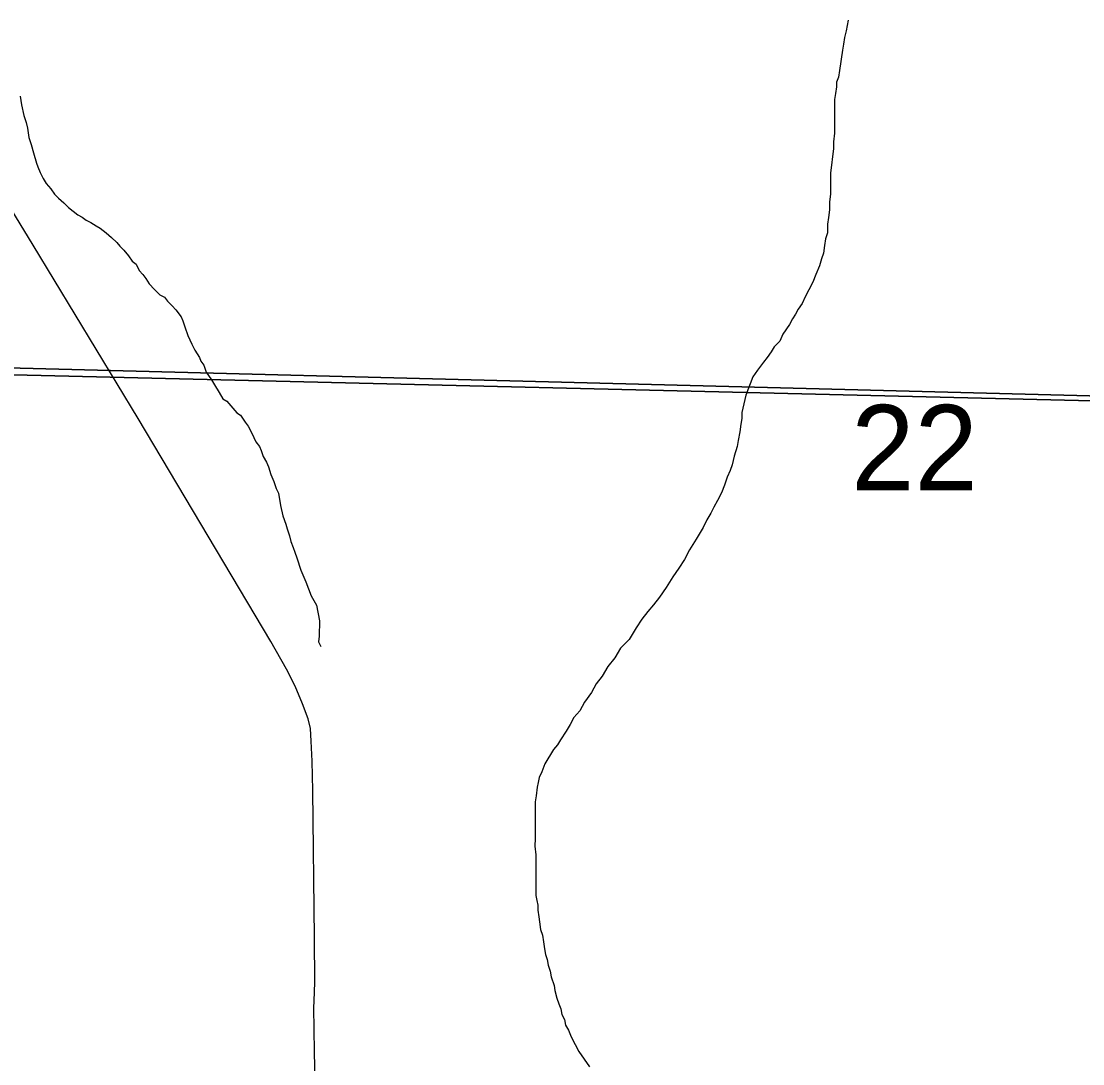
# Model space of a CAD drawing. Extents: x 0 to 68, y 0 to 52.9.
# Drawn here: x 47.168 to 47.718, y 37.512 to 38.053 of the extents above; entities that cross this region are included whole.
import ezdxf

# ---------------------------------------------------------------- set-up
doc = ezdxf.new("R2010")
doc.units = 0
for name, color, linetype in [('Default', 7, 'Continuous'), ('GM_X_Minor_River', 7, 'Continuous'), ('GM_X_Township', 7, 'Continuous'), ('GM_X_Township_Road', 7, 'Continuous')]:
    doc.layers.add(name, color=color, linetype=linetype)

msp = doc.modelspace()

# ---------------------------------------------------------------- linework, layer by layer
at = {"layer": 'Default'}
for points in [[(48.45764, 39.14733), (48.42638, 37.83913), (47.10596, 37.87106), (47.12776, 39.18296)], [(47.08147, 37.87185), (47.10596, 37.87106), (48.42638, 37.83913), (48.38433, 36.55233), (47.04294, 36.58651)]]:
    msp.add_lwpolyline(points, close=True, dxfattribs=at)
at = {"layer": 'GM_X_Minor_River'}
for points in [[(47.59672, 38.05354), (47.5957, 38.04803), (47.59469, 38.04452), (47.59418, 38.04101), (47.59367, 38.038), (47.59214, 38.02747), (47.59163, 38.02396), (47.59062, 38.02146), (47.59062, 38.01895), (47.59011, 38.01544), (47.5896, 38.01243), (47.58959, 38.00691), (47.58958, 38.0029), (47.58957, 37.99839), (47.58956, 37.99487), (47.58905, 37.99036), (47.58904, 37.98685), (47.58853, 37.98284), (47.58802, 37.97832), (47.58751, 37.97431), (47.58749, 37.96779), (47.58748, 37.96328), (47.58697, 37.95926), (47.58696, 37.95525), (47.58645, 37.95124), (47.58594, 37.94773), (47.58593, 37.94321), (47.58492, 37.94021), (47.58441, 37.9367), (47.5839, 37.93269), (47.58288, 37.92968), (47.58187, 37.92617), (47.57986, 37.92166), (47.57834, 37.91765), (47.57633, 37.91365), (47.57431, 37.91014), (47.5728, 37.90664), (47.57079, 37.90363), (47.56927, 37.90113), (47.56776, 37.89863), (47.56625, 37.89562), (47.56273, 37.89062), (47.56121, 37.88711), (47.5582, 37.88411), (47.55669, 37.88161), (47.55467, 37.8786), (47.55266, 37.8761), (47.54964, 37.8721), (47.54712, 37.86859), (47.54359, 37.85907), (47.54258, 37.85456), (47.54156, 37.85005), (47.54155, 37.84704), (47.54105, 37.84403), (47.54053, 37.84002), (47.53952, 37.83551), (47.53901, 37.8325), (47.5375, 37.82749), (47.53648, 37.82298), (47.53547, 37.81997), (47.53396, 37.81646), (47.53245, 37.81245), (47.53093, 37.80845), (47.52892, 37.80444), (47.5269, 37.80093), (47.52539, 37.79793), (47.52337, 37.79443), (47.52136, 37.79042), (47.51783, 37.78441), (47.51431, 37.7789), (47.51179, 37.77389), (47.50876, 37.76939), (47.50575, 37.76488), (47.50222, 37.75938), (47.4987, 37.75437), (47.49568, 37.75037)], [(47.16709, 38.01409), (47.16784, 38.00966), (47.16898, 38.00402), (47.17014, 38.00039), (47.17091, 37.99757), (47.17166, 37.99274), (47.17282, 37.98911)], [(47.17282, 37.98911), (47.17397, 37.98467), (47.17552, 37.97943), (47.1763, 37.97741), (47.17747, 37.97458), (47.17904, 37.97134), (47.18062, 37.96891), (47.183, 37.96607), (47.18498, 37.96323), (47.18697, 37.9612), (47.18976, 37.95875), (47.19214, 37.95631), (47.19693, 37.95263), (47.19933, 37.95139), (47.20133, 37.94976), (47.20373, 37.94852), (47.20653, 37.94688), (47.20853, 37.94564), (47.21172, 37.94319), (47.21451, 37.94074), (47.2173, 37.9383), (47.21888, 37.93627), (47.22087, 37.93423), (47.22325, 37.93139), (47.22523, 37.92855), (47.22722, 37.92692), (47.22879, 37.92368), (47.23078, 37.92164), (47.23237, 37.91961), (47.23394, 37.91678), (47.23673, 37.91393), (47.23951, 37.91108), (47.24191, 37.90985), (47.2435, 37.90782), (47.24589, 37.90537), (47.24787, 37.90334), (47.25065, 37.89969), (47.25143, 37.89767), (47.2526, 37.89444), (47.25415, 37.89), (47.25611, 37.88555), (47.25768, 37.88232), (47.26005, 37.87867), (47.26083, 37.87665), (47.26242, 37.87462), (47.26358, 37.87099), (47.26635, 37.86694), (47.26793, 37.8645), (47.27029, 37.86045), (47.27227, 37.85721), (47.27427, 37.85598), (47.27744, 37.85232), (47.27943, 37.84989), (47.28143, 37.84866), (47.2838, 37.84501), (47.28538, 37.84298), (47.28735, 37.83934), (47.28931, 37.83489), (47.29129, 37.83246), (47.29207, 37.83043), (47.29324, 37.82721), (47.29482, 37.82437), (47.29599, 37.82195), (47.29715, 37.81791), (47.29872, 37.81428), (47.29988, 37.81065), (47.30106, 37.80822), (47.30218, 37.80177), (47.30333, 37.79654), (47.30488, 37.7921), (47.30566, 37.78967), (47.30682, 37.78604), (47.30759, 37.78322), (47.30876, 37.77999), (47.30953, 37.77757), (47.31071, 37.77474), (47.31264, 37.76829), (47.31538, 37.76222), (47.31811, 37.75496), (47.32087, 37.7501), (47.32238, 37.74204), (47.32228, 37.73401), (47.32184, 37.7312), (47.32184, 37.7312), (47.32302, 37.72877)], [(47.49568, 37.75037), (47.49266, 37.74687), (47.48964, 37.74286), (47.48662, 37.73836), (47.48309, 37.73235), (47.47857, 37.72785), (47.47555, 37.72284), (47.47202, 37.71834), (47.469, 37.71333), (47.46598, 37.70933), (47.46346, 37.70482), (47.45994, 37.69981), (47.45742, 37.69531), (47.4544, 37.69181), (47.45239, 37.6883), (47.45037, 37.6848), (47.44735, 37.68029), (47.44584, 37.67779), (47.44383, 37.67529), (47.4393, 37.66778), (47.43778, 37.66377), (47.43627, 37.66076), (47.43576, 37.65826), (47.43526, 37.65575), (47.43474, 37.65123), (47.43423, 37.64823), (47.43423, 37.64572), (47.43422, 37.64271), (47.43421, 37.6397), (47.43421, 37.63669), (47.4342, 37.63268), (47.43419, 37.62916), (47.43418, 37.62515), (47.43467, 37.62064), (47.43466, 37.61712), (47.43465, 37.61261), (47.43464, 37.60759), (47.43463, 37.60308), (47.43462, 37.59957), (47.43512, 37.59706), (47.43561, 37.59454), (47.43561, 37.59204), (47.4361, 37.58853), (47.4366, 37.58601), (47.43709, 37.582), (47.43809, 37.57899), (47.43858, 37.57547), (47.43908, 37.57196), (47.43957, 37.56895), (47.44057, 37.56644), (47.44106, 37.56343), (47.44206, 37.56041), (47.44256, 37.5574), (47.44405, 37.55288), (47.44454, 37.55037), (47.44554, 37.54636), (47.44654, 37.54334), (47.44753, 37.54083), (47.44803, 37.53782), (47.44953, 37.53531), (47.45002, 37.53229), (47.45152, 37.52978), (47.45302, 37.52627), (47.45502, 37.52225), (47.45701, 37.51873), (47.46251, 37.51069)]]:
    msp.add_lwpolyline(points, dxfattribs=at)
at = {"layer": 'GM_X_Township'}
for points in [[(50.34506, 37.77433), (49.87003, 37.78728), (49.7424, 37.78907), (49.09193, 37.81286), (48.42924, 37.83782), (47.97584, 37.8521), (47.09341, 37.87493), (46.43542, 37.88698), (45.78152, 37.90751), (45.76356, 37.9078), (44.77759, 37.93161), (44.12143, 37.94309), (43.3203, 37.94792), (43.31455, 37.9477), (43.13228, 37.95106), (43.13722, 38.12535), (43.1394, 38.18651), (43.13947, 38.19396), (43.15039, 38.61621), (43.15805, 38.89613)], [(44.77759, 37.93161), (45.76356, 37.9078), (45.78152, 37.90751), (46.43542, 37.88698), (47.09341, 37.87493), (47.97584, 37.8521), (48.42924, 37.83782), (49.09193, 37.81286), (49.7424, 37.78907), (49.71566, 36.99716), (49.70773, 36.74798), (49.69511, 36.18054), (49.68722, 35.85214), (49.65449, 34.5254), (49.63258, 33.86577), (49.61888, 33.2067), (49.60976, 32.7683)]]:
    msp.add_lwpolyline(points, dxfattribs=at)
at = {"layer": 'GM_X_Township_Road'}
msp.add_lwpolyline([(47.3201, 37.50237), (47.31979, 37.51875), (47.31945, 37.54155), (47.3197, 37.54481), (47.31998, 37.55471), (47.31974, 37.57761), (47.31893, 37.65412), (47.31853, 37.66919), (47.31799, 37.67962), (47.31775, 37.6862), (47.31659, 37.69121), (47.31357, 37.69892), (47.30976, 37.70808), (47.30526, 37.71692), (47.2971, 37.73123), (47.22832, 37.847), (47.1739, 37.9369), (47.13262, 38.00403)], dxfattribs=at)

# ---------------------------------------------------------------- texts
at = {"layer": 'Default'}
msp.add_text('22', height=0.0442, rotation=0, dxfattribs=at).set_placement((47.59821, 37.80977))

doc.saveas('drawing.dxf')
